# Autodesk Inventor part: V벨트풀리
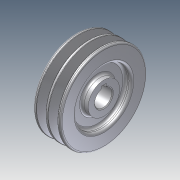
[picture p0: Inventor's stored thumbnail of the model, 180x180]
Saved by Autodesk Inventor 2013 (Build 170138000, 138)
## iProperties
Company: 한국ATC센터
Created: 2015-02
Part Number: V벨트풀리
Document SubType Name: Modeling
Designer: KYOUNG IL JANG
Density: 1 g/cm^3
Material: 일반
Author: KYOUNG IL JANG
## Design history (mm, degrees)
sketch "스케치1"
  geometry: L1 (0, 0)-(35, 0); L2 (35, 0)-(35, 55); L3 (35, 55)-(31.062, 55); L4 (31.062, 55)-(27.001, 42.5); L5 (27.001, 42.5)-(22.999, 42.5); L6 (22.999, 42.5)-(18.938, 55); L7 (18.938, 55)-(16.062, 55); L8 (16.062, 55)-(12.001, 42.5); L9 (12.001, 42.5)-(7.999, 42.5); L10 (7.999, 42.5)-(3.938, 55); L11 (3.938, 55)-(0, 55); L12 (0, 55)-(0, 0); L13 (5.4, 50.5)-(14.6, 50.5); L14 (20.4, 50.5)-(29.6, 50.5); 3 further points
  constraints: 28 end point, 8 parallel, 6 collinear, 4 point on line, 3 midpoint, 2 perpendicular, 1 horizontal, 1 vertical alignment
  dimensions: "d0" = 36 deg angle of L8 L10; "d1" = 9.2 distance of L14.start L14.end; "d2" = 4.5 distance between parallel lines of L13 L11; "d3" = 8 distance between parallel lines of L9 L13; "d4" = 10 distance from line of point (25, 42.5) L2; "d5" = 15 distance of point (25, 42.5) point (10, 42.5); "d6" = 35 distance of L1.start L1.end; "d7" = 101 diameter of L14 L1
revolve "회전1" sketch "스케치1" stored, may be unused: angle "d8" = 90 deg
fillet "모깎기1" dims "d9" = 2
fillet "모깎기2" dims "d10" = 0.5
fillet "모깎기3" dims "d11" = 1
sketch "스케치2"
  geometry: L1 (0, 0)-(8, 0); L2 (8, 0)-(8, 20); L3 (8, 20)-(17, 20); L4 (17, 20)-(17, 35); L5 (17, 35)-(0, 35); L6 (0, 35)-(0, 0); L7 (35, 35)-(27, 35); L8 (27, 35)-(27, 20); L9 (27, 20)-(35, 20); L10 (35, 20)-(35, 35); L11 (35, 53)-(35, -53) reference
  constraints: 20 end point, 6 parallel, 3 collinear, 3 perpendicular, 1 horizontal
  dimensions: "d12" = 40 diameter of L9 L1; "d13" = 70 diameter of L7 L1; "d14" = 8 distance between parallel lines of L10 L8; "d15" = 10 distance between parallel lines of L8 L4; "d16" = 9 distance between parallel lines of L4 L2
revolve "회전2" sketch "스케치2" stored, may be unused: angle "d17" = 90 deg
hole "구멍1" diameter "d20" = 22; stored, may be unused: countersink angle "d24" = 90 deg, drill point angle "d26" = 118 deg; dims "d18" = 10, "d19" = 10, "d21" = 6, "d22" = 4, "d23" = 2, "d25" = 8
sketch "스케치3"
  geometry: L1 (-14.8, -3)-(-7.8, -3); L2 (-7.8, -3)-(-7.8, 3); L3 (-7.8, 3)-(-14.8, 3); L4 (-14.8, 3)-(-14.8, -3); C1 r 11 at (0, 0) reference; 2 further points
  constraints: 8 end point, 2 parallel, 1 horizontal, 1 horizontal alignment, 1 midpoint, 1 perpendicular
  dimensions: "d27" = 25.8 dimension on C1 L4; "d28" = 6 distance of L3.end L1.start; "d29" = 7 distance between parallel lines of L4 L2
extrude "돌출1" cut sketch "스케치3" stored distance "d30" = 10; taper "d31" = 0 deg
fillet "모깎기4" dims "d32" = 3
chamfer "모따기1" distance "d33" = 1; stored, may be unused: second distance "d34" = 2, angle "d35" = 45 deg
node "솔리드1"
